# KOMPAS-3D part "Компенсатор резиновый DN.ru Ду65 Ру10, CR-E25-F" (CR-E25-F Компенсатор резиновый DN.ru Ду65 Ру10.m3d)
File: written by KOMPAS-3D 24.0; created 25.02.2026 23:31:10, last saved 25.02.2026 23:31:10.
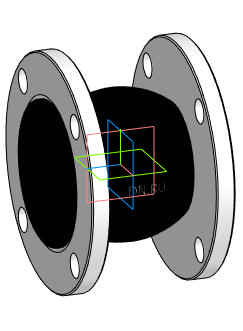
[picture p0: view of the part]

Document properties: Автор: DN.RU; Полное имя файла: D:\PROJECT CAD\DN.RU\...178(4)(ACTUALE). CR-E25-F Компенсатор резиновый DN.ru Ру10-16\DN65_PN10\CR-E25-F Компенсатор резиновый DN.ru Ду65 Ру10.m3d

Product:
- Body: Твердое тело2  | qty 1
    Масса: 7.29646
- Part/product: Компенсатор резиновый DN.ru Ду65 Ру10  | designation CR-E25-F
    Масса: 5.88
    Раздел спецификации: Прочие изделия
    Комментарий: D140-02163
    Примечание: D140-02163
    additional columns: Типовые

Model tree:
1. Твердое тело2  (labels: Твердое тело2)

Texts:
  CR-E25-F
